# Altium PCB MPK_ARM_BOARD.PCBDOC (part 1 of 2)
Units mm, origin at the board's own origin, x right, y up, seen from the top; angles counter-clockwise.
Board outline 120 x 100 mm, 2 copper layers (Top Layer, Bottom Layer); 129 components, 139 nets, 526 pads, 161 vias.
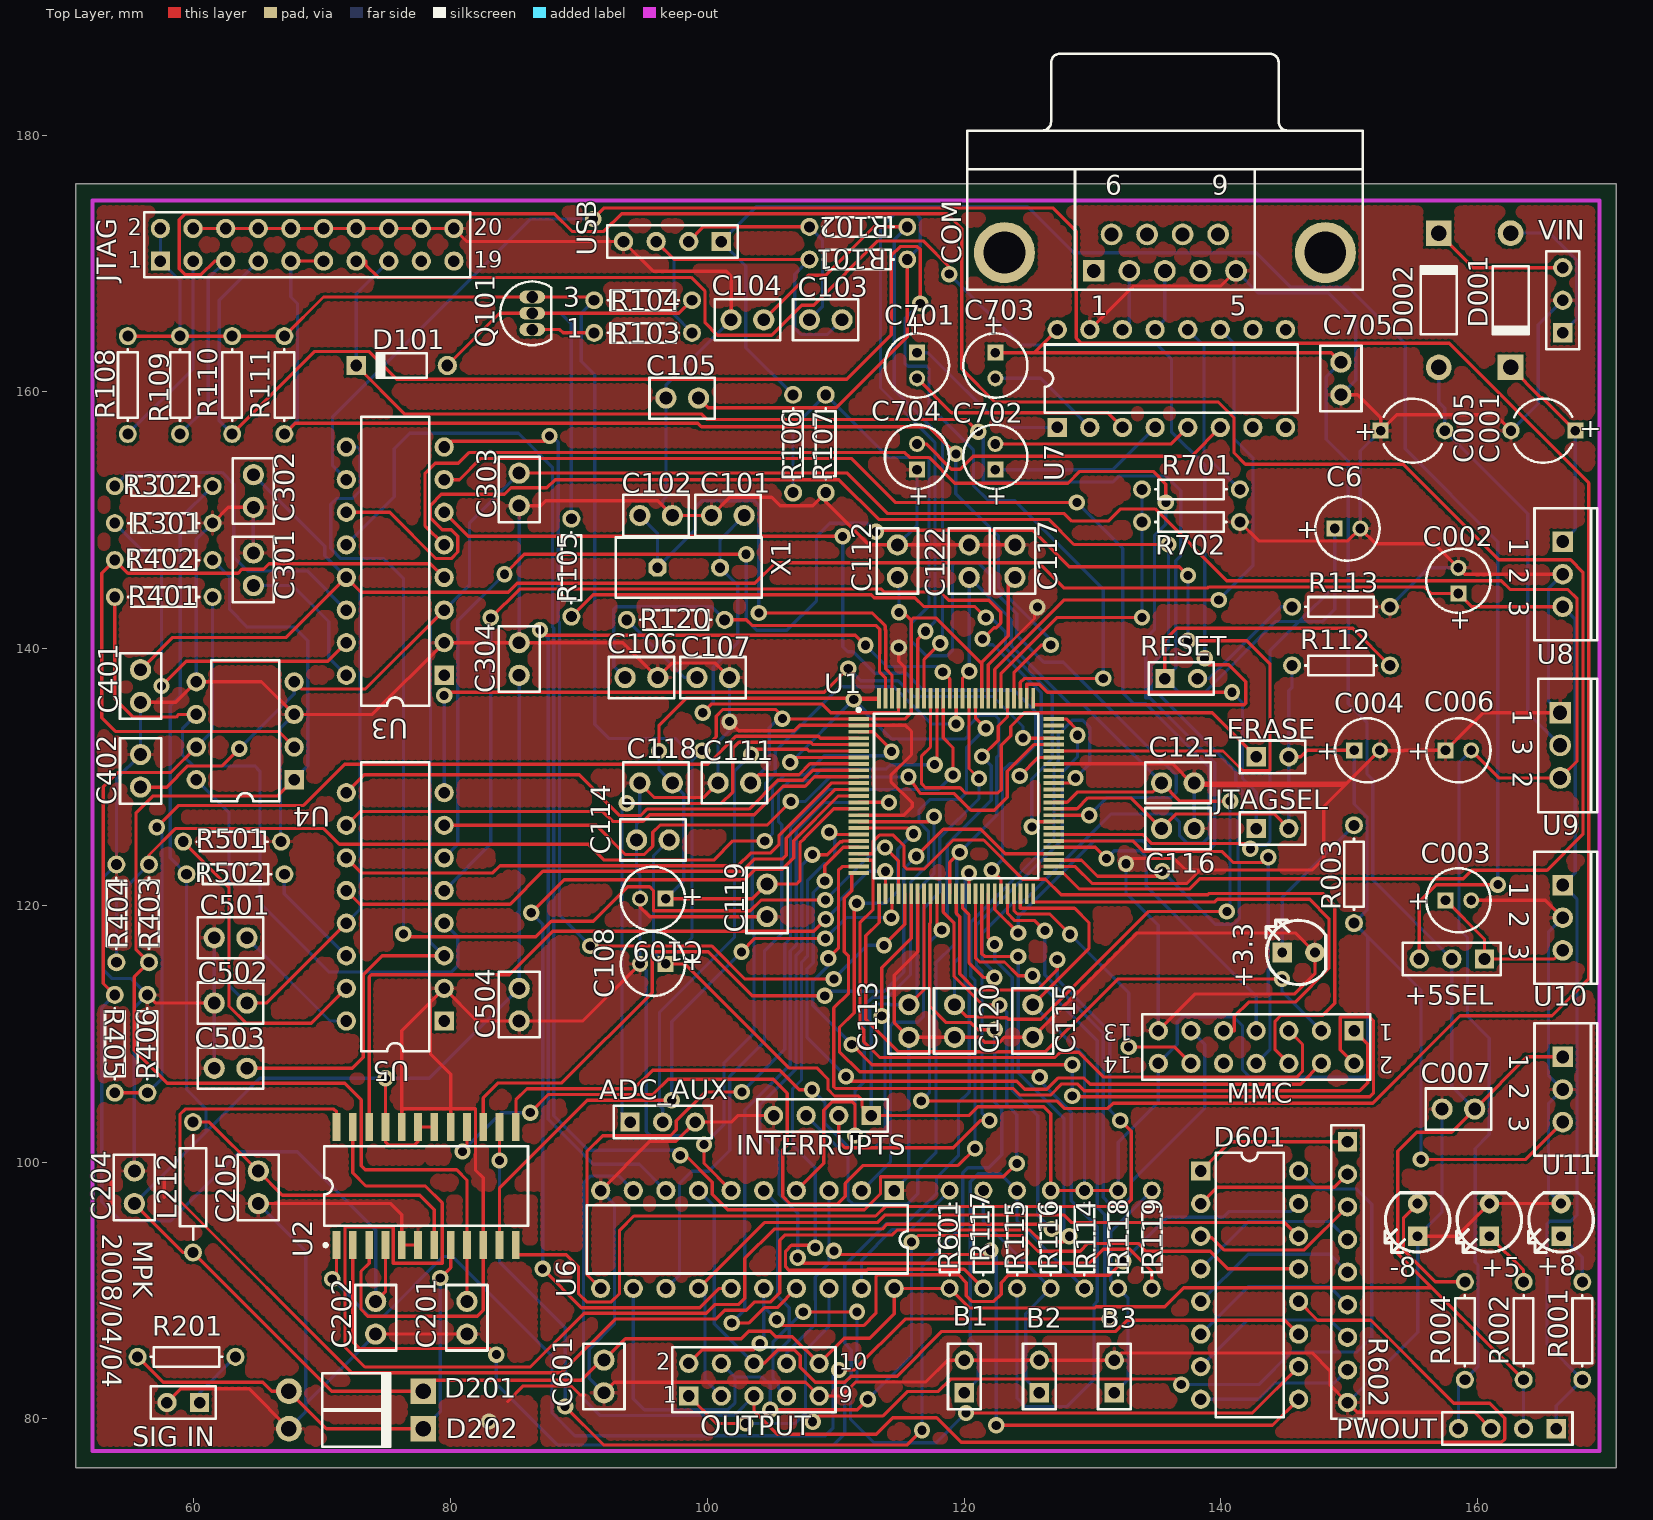
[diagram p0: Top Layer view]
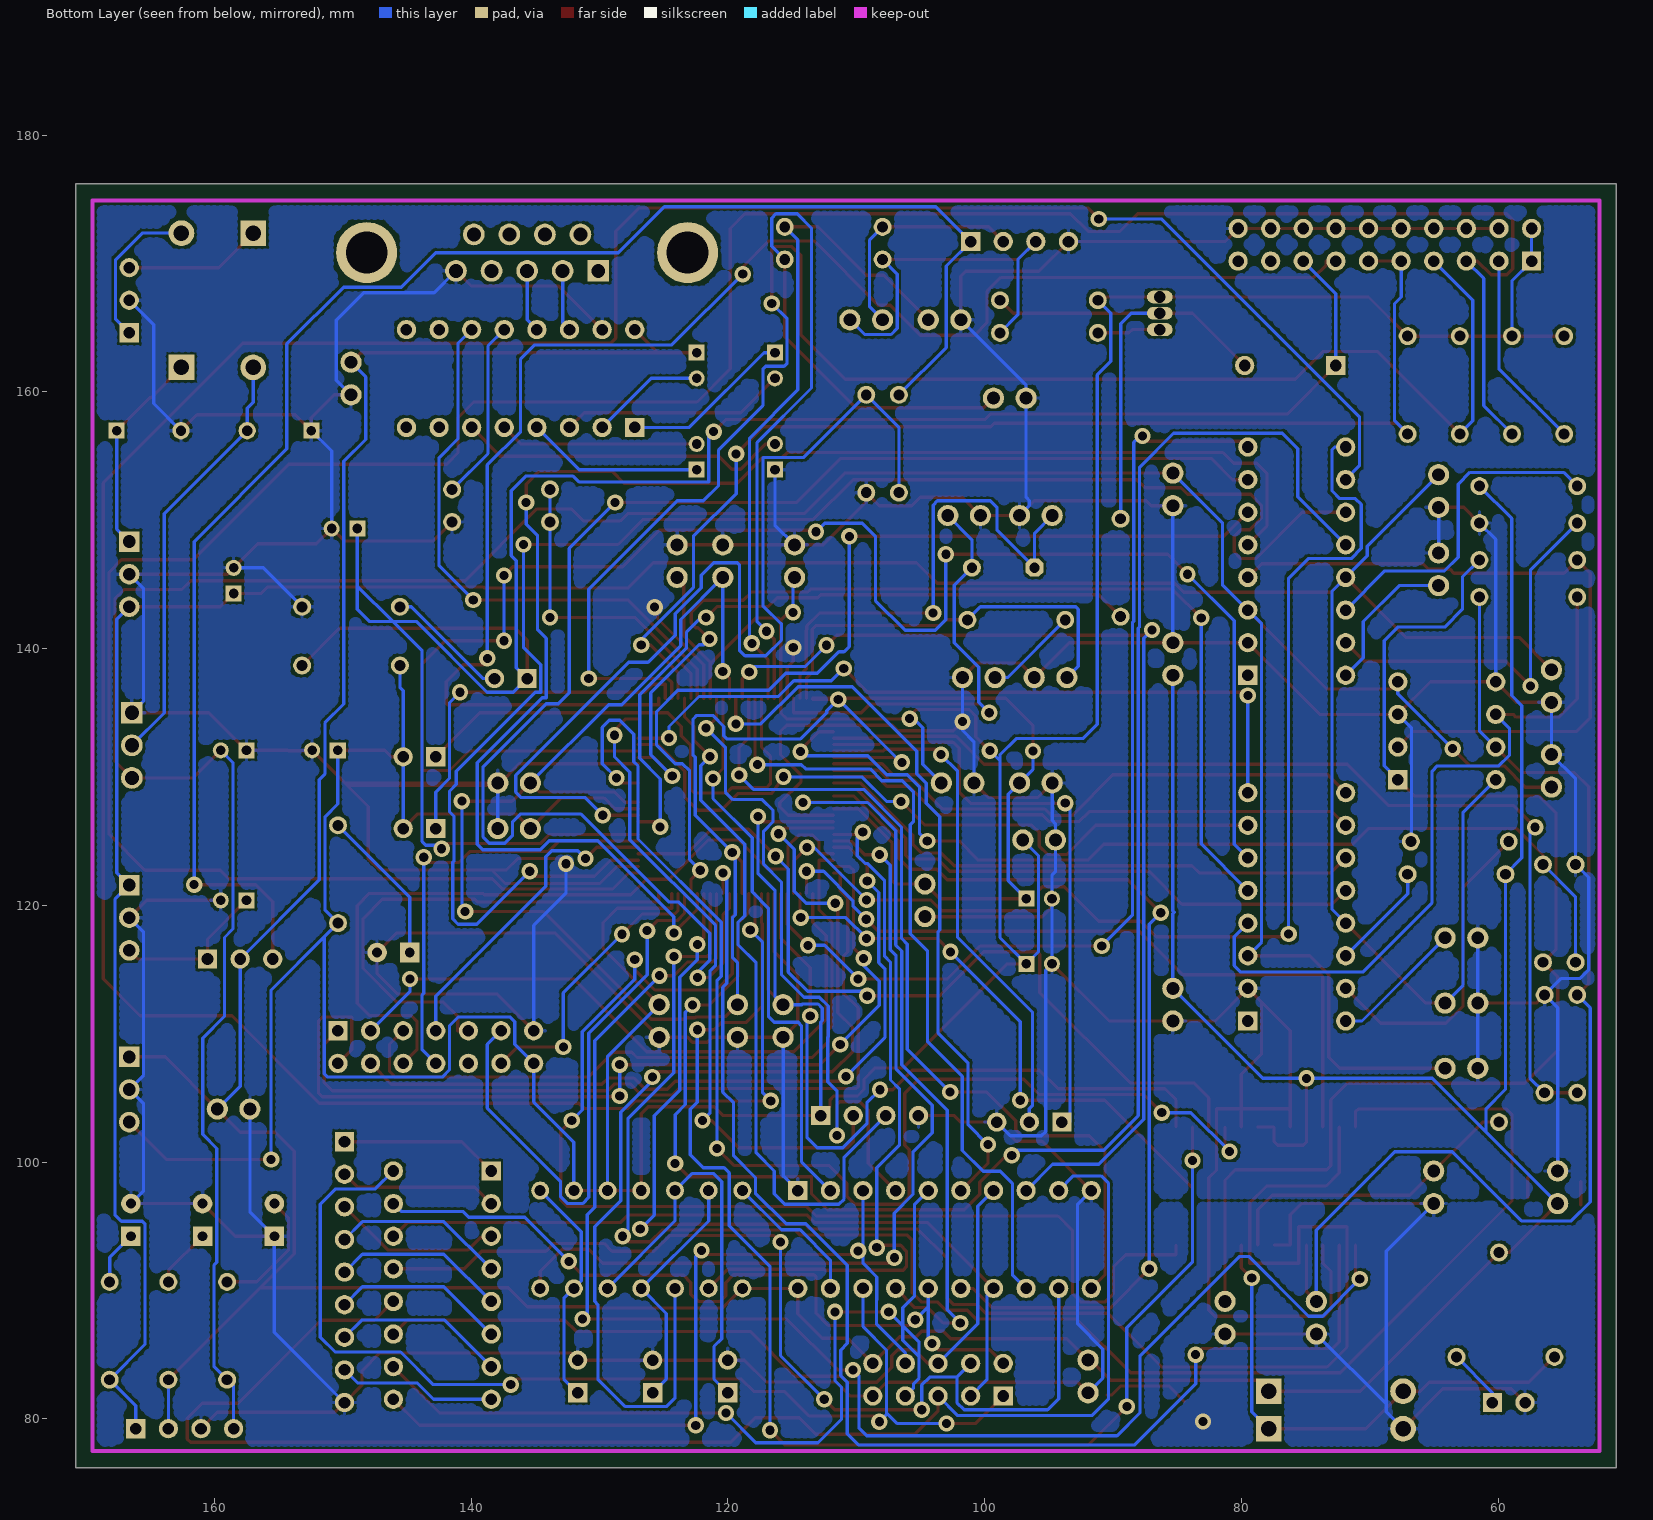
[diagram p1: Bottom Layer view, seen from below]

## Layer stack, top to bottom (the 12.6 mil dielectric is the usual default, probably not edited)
Top Layer: signal copper 0.0356
Dielectric: dielectric 0.32, FR-4, Dk 4.8
Bottom Layer: signal copper 0.0356

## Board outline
50.8,76.2 170.8,76.2 170.8,176.2 50.8,176.2

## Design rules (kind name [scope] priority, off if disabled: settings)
Clearance Clearance_1 [(InNet('-8V') AND InNet('+5V') AND InNet('+5V_USB') AND InNet('+8V'))] p1: gap=0.4
Clearance [All] p2: gap=0.18
ComponentClearance [All] p1: gap=0.254 collisioncheckmode=0
PolygonConnect [All] p1: connectstyle=Relief reliefconductorwidth=0.254 reliefentries=4 polygonreliefangle="90 Angle"
RoutingLayers [All] p1: top layer=Horizontal bottom layer=Vertical
RoutingVias [All] p1: holewidth=0.711 width=1.27 viastyle="Through Hole" minholewidth=0.711 minwidth=1.27 maxholewidth=0.711 maxwidth=1.27
SolderMaskExpansion [All] p1: expansion=0.102
TestPointUsage [All] p1: valid=0 allowmultiple=FALSE
Testpoint [All] p1: side=15 testpointundercomponent=TRUE minsize=1.016 maxsize=2.54 preferedsize=1.524 minholesize=0 maxholesize=1.016 preferedholesize=0.813 testpointgrid=0.025 style=1023 order=1234567890
Width Width_1 [(InNet('-8V') AND InNet('+8V') AND InNet('+5V')) AND InNet('+5V_USB')] p1: maxlimit=0.4 minlimit=0.3 preferedwidth=0.3
Width [All] p2: maxlimit=0.254 minlimit=0.18 preferedwidth=0.254
16 further rules are at their usual default settings.

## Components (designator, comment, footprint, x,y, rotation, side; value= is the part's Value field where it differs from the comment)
+3.3 "LED" LED 144.78,116.332 r90 top (schematic designator PW+3.3)
+5 "LED" LED 160.909,94.234 r180 top (schematic designator PW+5)
+5SEL "Header 3" HDR1X3 160.528,115.824 r180 top (schematic designator +5V_SELECT)
+8 "LED" LED 166.497,94.234 r180 top (schematic designator PW+8)
-8 "LED" LED 155.321,94.234 r180 top (schematic designator PW-8)
ADC_AUX "Header 3" HDR1X3 93.98,103.124 r0 top
B1 "Header 2" HDR1X2 120.015,82.042 r90 top
B2 "Header 2" HDR1X2 125.857,82.042 r90 top
B3 "Header 2" HDR1X2 131.699,82.042 r90 top
C001 "Cap Pol1" CAPPR5-5X5 165.1,156.972 r180 top
C002 "Cap Pol1" CAPPR2-5X6.8 158.496,145.288 r90 top
C003 "Cap Pol1" CAPPR2-5X6.8 158.496,120.396 r0 top
C004 "Cap Pol1" CAPPR2-5X6.8 151.384,132.08 r0 top
C005 "Cap Pol1" CAPPR5-5X5 154.94,156.972 r0 top
C6 "Cap Pol1" CAPPR2-5X6.8 149.86,149.352 r0 top
C006 "Cap Pol1" CAPPR2-5X6.8 158.496,132.079 r0 top
C007 "Cap" CAPR2.54-5.1X3.2 158.496,104.14 r0 top
C101 "Cap" CAPR2.54-5.1X3.2 101.6,150.368 r180 top
C102 "Cap" CAPR2.54-5.1X3.2 96.012,150.368 r0 top
C103 "Cap" CAPR2.54-5.1X3.2 109.22,165.608 r0 top
C104 "Cap" CAPR2.54-5.1X3.2 103.124,165.608 r0 top
C105 "Cap" CAPR2.54-5.1X3.2 98.044,159.512 r0 top
C106 "Cap" CAPR2.54-5.1X3.2 94.869,137.744 r180 top
C107 "Cap" CAPR2.54-5.1X3.2 100.457,137.744 r180 top
C108 "Cap Pol1" CAPPR2-5X6.8 95.758,115.443 r180 top
C109 "Cap Pol1" CAPPR2-5X6.8 95.758,120.523 r180 top
C111 "Cap" CAPR2.54-5.1X3.2 102.108,129.54 r0 top
C112 "Cap" CAPR2.54-5.1X3.2 114.808,146.812 r270 top
C113 "Cap" CAPR2.54-5.1X3.2 115.697,110.998 r90 top
C114 "Cap" CAPR2.54-5.1X3.2 95.758,125.095 r0 top
C115 "Cap" CAPR2.54-5.1X3.2 125.349,110.998 r90 top
C116 "Cap" CAPR2.54-5.1X3.2 136.652,125.984 r180 top
C117 "Cap" CAPR2.54-5.1X3.2 123.952,146.812 r270 top
C118 "Cap" CAPR2.54-5.1X3.2 96.012,129.54 r0 top
C119 "Cap" CAPR2.54-5.1X3.2 104.648,120.396 r90 top
C120 "Cap" CAPR2.54-5.1X3.2 119.253,110.998 r90 top
C121 "Cap" CAPR2.54-5.1X3.2 136.652,129.54 r180 top
C122 "Cap" CAPR2.54-5.1X3.2 120.396,146.812 r270 top
C201 "Cap" CAPR2.54-5.1X3.2 81.28,87.884 r90 top
C202 "Cap" CAPR2.54-5.1X3.2 74.168,87.884 r90 top
C204 "Cap" CAPR2.54-5.1X3.2 55.372,98.044 r270 top
C205 "Cap" CAPR2.54-5.1X3.2 65.024,98.044 r90 top
C301 "Cap" CAPR2.54-5.1X3.2 64.643,146.177 r270 top
C302 "Cap" CAPR2.54-5.1X3.2 64.643,152.273 r90 top
C303 "Cap" CAPR2.54-5.1X3.2 85.344,152.4 r270 top
C304 "Cap" CAPR2.54-5.1X3.2 85.344,139.192 r270 top
C401 "Cap" CAPR2.54-5.1X3.2 55.855,137.084 r90 top
C402 "Cap" CAPR2.54-5.1X3.2 55.855,130.48 r90 top
C501 "Cap" CAPR2.54-5.1X3.2 62.865,117.475 r0 top
C502 "Cap" CAPR2.54-5.1X3.2 62.865,112.395 r0 top
C503 "Cap" CAPR2.54-5.1X3.2 62.865,107.315 r180 top
C504 "Cap" CAPR2.54-5.1X3.2 85.344,112.268 r90 top
C601 "Cap" CAPR2.54-5.1X3.2 91.948,83.312 r90 top
C701 "Cap Pol1" CAPPR2-5X6.8 116.332,162.052 r270 top
C702 "Cap Pol1" CAPPR2-5X6.8 122.428,154.94 r90 top
C703 "Cap Pol1" CAPPR2-5X6.8 122.428,162.052 r270 top
C704 "Cap Pol1" CAPPR2-5X6.8 116.332,154.94 r90 top
C705 "Cap" CAPR2.54-5.1X3.2 149.352,161.036 r90 top
COM "D Connector 9" DSUB1.385-2H9 135.636,180.34 r0 top (schematic designator J1)
D001 "Diode 1N4007" DIO10.46-5.3x2.8 162.56,167.132 r270 top
D002 "Diode 1N4007" DIO10.46-5.3x2.8 156.972,167.132 r90 top
D101 "Diode 1N4148" DIO7.1-3.9x1.9 76.2,162.052 r180 top
D201 "Diode 1N4004" DIO10.46-5.3x2.8 72.644,82.169 r0 top
D202 "Diode 1N4004" DIO10.46-5.3x2.8 72.644,79.248 r0 top
D601 "Res Pack2" DIP-16 142.24,90.424 r270 top
ERASE "Header 2" HDR1X2 142.748,131.572 r0 top
INTERRUPTS "Header 4" HDR1X4 112.776,103.632 r180 top
JTAG "Header 10X2" HDR2X10 57.404,170.18 r0 top
JTAGSEL "Header 2" HDR1X2 142.748,125.984 r0 top
L212 "Res2" AXIAL-0.4 59.944,98.044 r90 top
MMC "Header 7X2" HDR2X7 150.368,110.236 r180 top
OUTPUT "Header 5X2" HDR2X5 98.552,81.788 r0 top
PWOUT "Header 4" HDR1X4 166.116,79.248 r180 top
Q101 "2N3904" BCY-W3/E4 86.36,166.116 r0 top
R001 "Res1" AXIAL-0.3 168.148,86.868 r270 top
R002 "Res1" AXIAL-0.3 163.576,86.868 r270 top
R003 "Res1" AXIAL-0.3 150.368,122.428 r270 top
R004 "Res1" AXIAL-0.3 159.004,86.868 r270 top
R101 "Res1" AXIAL-0.3 111.76,170.307 r180 top
R102 "Res1" AXIAL-0.3 111.76,172.847 r180 top
R103 "Res1" AXIAL-0.3 94.996,164.592 r180 top
R104 "Res1" AXIAL-0.3 94.996,167.132 r180 top
R105 "Res1" AXIAL-0.3 89.408,146.304 r90 top
R106 "Res1" AXIAL-0.3 106.68,155.956 r90 top
R107 "Res1" AXIAL-0.3 109.22,155.956 r90 top
R108 "Res1" AXIAL-0.3 54.864,160.528 r90 top
R109 "Res1" AXIAL-0.3 58.928,160.528 r90 top
R110 "Res1" AXIAL-0.3 62.992,160.528 r90 top
R111 "Res1" AXIAL-0.3 67.056,160.528 r90 top
R112 "Res1" AXIAL-0.3 149.352,138.684 r180 top
R113 "Res1" AXIAL-0.3 149.352,143.256 r180 top
R114 "Res1" AXIAL-0.3 129.371,93.98 r90 top
R115 "Res1" AXIAL-0.3 124.121,93.98 r90 top
R116 "Res1" AXIAL-0.3 126.746,93.98 r90 top
R117 "Res1" AXIAL-0.3 121.497,93.98 r90 top
R118 "Res1" AXIAL-0.3 131.995,93.98 r90 top
R119 "Res1" AXIAL-0.3 134.62,93.98 r90 top
R120 "Res1" AXIAL-0.3 97.536,142.24 r0 top
R201 "Res1" AXIAL-0.3 59.436,84.836 r180 top
R301 "Res1" AXIAL-0.3 57.658,149.775 r180 top
R302 "Res1" AXIAL-0.3 57.658,152.654 r180 top
R401 "Res1" AXIAL-0.3 57.658,144.018 r180 top
R402 "Res1" AXIAL-0.3 57.658,146.897 r180 top
R403 "Res1" AXIAL-0.3 56.515,119.38 r270 top
R404 "Res1" AXIAL-0.3 53.975,119.38 r270 top
R405 "Res1" AXIAL-0.3 53.848,109.22 r90 top
R406 "Res1" AXIAL-0.3 56.388,109.22 r270 top
R501 "Res1" AXIAL-0.3 62.992,124.968 r180 top
R502 "Res1" AXIAL-0.3 63.246,122.428 r0 top
R601 "Res1" AXIAL-0.3 118.872,93.98 r270 top
R602 "Header 9" HDR1X9 149.86,101.6 r270 top
R701 "Res1" AXIAL-0.3 137.668,152.4 r180 top
R702 "Res1" AXIAL-0.3 137.668,149.86 r180 top
RESET "Header 2" HDR1X2 135.636,137.668 r0 top
"SIG IN" "Header 2" HDR1X2 60.452,81.28 r180 top (schematic designator "SIGNAL IN")
U1 "AT91SAM7X256" LQFP100 119.38,128.524 r0 top
U2 "TDA8714" SOP24 70.104,94.996 r90 top
U3 "DAC0808LCN" N16A 75.692,146.812 r90 top
U4 "AD706AN" N-8_A 64.008,133.604 r90 top
U5 "DAC0808LCN" N16A 75.692,119.888 r90 top
U6 "SN74HC244N" N020 103.124,93.98 r180 top
U7 "MAX232ACPE" PE16A 136.144,161.036 r0 top
U8 "MC78M08BT" 221A-04 166.624,145.796 r270 top
U9 "L7908ACV" TO220V 166.424,132.469 r270 top
U10 "MC7805ACT" 221A-04 166.624,119.041 r270 top
U11 "LM340T-18" 221A-04 166.624,105.664 r270 top
USB "Header 4" HDR1X4 101.092,171.704 r180 top
VIN "Header 3" HDR1X3 166.624,164.592 r90 top
X1 "ECS-10-13-1" HC-49U 98.552,146.304 r0 top

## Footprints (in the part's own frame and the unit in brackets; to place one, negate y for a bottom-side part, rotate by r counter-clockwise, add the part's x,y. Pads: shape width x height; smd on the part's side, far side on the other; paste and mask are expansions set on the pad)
221A-04 [mm] "TO, Thru-Hole, Vertical, Heatsink Mounted; 3 In-Line Leads; Pitch 2.54 mm"
  rect 1.6x1.6 hole 1: 1(-2.54,0)
  round 1.6 hole 1: 2(0,0) 3(2.54,0)
  silkscreen extent -5.15,-2.2 5.15,2.7
AXIAL-0.3 [mm]
  round 1.4 hole 0.85: 1(-3.81,0) 2(3.81,0)
  silkscreen extent -2.77,-0.76 2.77,0.76
AXIAL-0.4 [mm]
  round 1.4 hole 0.85: 1(-5.08,0) 2(5.08,0)
  silkscreen extent -4.06,-1.02 4.06,1.02
BCY-W3/E4 [mm]
  oval 2x1 hole 0.9: 1(0,-1.27) 2(0,0) 3(0,1.27)
  silkscreen extent -2.48,-2.48 1.5,2.48
CAPPR2-5X6.8 [mm]
  rect 1.25x1.25 hole 0.75: 1(-1,0)
  round 1.25 hole 0.75: 2(1,0)
  silkscreen extent -2.5,-2.5 2.5,2.5
CAPPR5-5X5 [mm]
  rect 1.25x1.25 hole 0.75: 1(-2.5,0)
  round 1.35 hole 0.8: 2(2.5,0)
  silkscreen extent -2.26,-2.5 2.27,2.5
CAPR2.54-5.1X3.2 [mm]
  round 1.65 hole 1: 1(-1.27,0) 2(1.27,0)
  silkscreen extent -2.55,-1.6 2.55,1.6
DIO7.1-3.9x1.9 [mm]
  round 1.5 hole 0.9: 1(-3.55,0)
  rect 1.5x1.5 hole 0.9: 2(3.55,0)
  silkscreen extent -1.95,-0.95 2.05,0.95
DIO10.46-5.3x2.8 [mm]
  round 2 hole 1.2: 1(-5.23,0)
  rect 2x2 hole 1.2: 2(5.23,0)
  silkscreen extent -2.65,-1.4 2.75,1.4
DIP-16 [mm]
  rect 1.5x1.5 hole 0.9: 1(-8.89,-3.81)
  round 1.5 hole 0.9: 2(-6.35,-3.81) 3(-3.81,-3.81) 4(-1.27,-3.81) 5(1.27,-3.81) 6(3.81,-3.81) 7(6.35,-3.81) 8(8.89,-3.81) 9(8.89,3.81) 10(6.35,3.81) 11(3.81,3.81) 12(1.27,3.81) 13(-1.27,3.81) 14(-3.81,3.81) 15(-6.35,3.81) 16(-8.89,3.81)
  silkscreen extent -10.3,-2.65 10.3,2.65
DSUB1.385-2H9 [mm] "Connector; D Subminiature; 9 Position; Right Angle; Pitch 1.385 mm"
  rect 1.69x1.69 hole 1.09: 1(-5.54,-10.92)
  round 1.69 hole 1.09: 2(-2.77,-10.92) 3(0,-10.92) 4(2.77,-10.92) 5(5.54,-10.92) 6(-4.155,-8.08) 7(-1.385,-8.08) 8(1.385,-8.08) 9(4.155,-8.08)
  round 4.76 hole 3.26: 10(-12.495,-9.5) 11(12.495,-9.5)
  silkscreen extent -15.4,-12.4 15.4,6
HC-49U [mm] "Quartz Crystal, Thru-Hole; 2 Leads; Body 11.35 x 4.65 x 13.46 mm (LxWxH max)"
  oct 1.4x1.4 hole 0.8: 1(-2.44,0)
  round 1.4 hole 0.8: 2(2.44,0)
  silkscreen extent -5.7,-2.35 5.7,2.35
HDR1X2 [mm] "Connector; Header; 2 Position"
  rect 1.5x1.5 hole 0.9: 1(0,0)
  round 1.5 hole 0.9: 2(2.54,0)
  silkscreen extent -1.27,-1.27 3.81,1.27
HDR1X3 [mm] "Connector; Header; 3 Position"
  rect 1.5x1.5 hole 0.9: 1(0,0)
  round 1.5 hole 0.9: 2(2.54,0) 3(5.08,0)
  silkscreen extent -1.27,-1.27 6.35,1.27
HDR1X4 [mm] "Connector; Header; 4 Position"
  rect 1.5x1.5 hole 0.9: 1(0,0)
  round 1.5 hole 0.9: 2(2.54,0) 3(5.08,0) 4(7.62,0)
  silkscreen extent -1.27,-1.27 8.89,1.27
HDR1X9 [mm] "Connector; Header; 9 Position"
  rect 1.5x1.5 hole 0.9: 1(0,0)
  round 1.5 hole 0.9: 2(2.54,0) 3(5.08,0) 4(7.62,0) 5(10.16,0) 6(12.7,0) 7(15.24,0) 8(17.78,0) 9(20.32,0)
  silkscreen extent -1.27,-1.27 21.59,1.27
HDR2X5 [mm] "Connector; Header; 5x2 Position"
  rect 1.5x1.5 hole 0.9: 1(0,0)
  round 1.5 hole 0.9: 2(0,2.54) 3(2.54,0) 4(2.54,2.54) 5(5.08,0) 6(5.08,2.54) 7(7.62,0) 8(7.62,2.54) 9(10.16,0) 10(10.16,2.54)
  silkscreen extent -1.27,-1.27 11.43,3.81
HDR2X7 [mm] "Connector; Header; 7x2 Position"
  rect 1.5x1.5 hole 0.9: 1(0,0)
  round 1.5 hole 0.9: 2(0,2.54) 3(2.54,0) 4(2.54,2.54) 5(5.08,0) 6(5.08,2.54) 7(7.62,0) 8(7.62,2.54) 9(10.16,0) 10(10.16,2.54) 11(12.7,0) 12(12.7,2.54) 13(15.24,0) 14(15.24,2.54)
  silkscreen extent -1.27,-1.27 16.51,3.81
HDR2X10 [mm] "Connector; Header; 10x2 Position"
  rect 1.5x1.5 hole 0.9: 1(0,0)
  round 1.5 hole 0.9: 2(0,2.54) 3(2.54,0) 4(2.54,2.54) 5(5.08,0) 6(5.08,2.54) 7(7.62,0) 8(7.62,2.54) 9(10.16,0) 10(10.16,2.54) 11(12.7,0) 12(12.7,2.54) 13(15.24,0) 14(15.24,2.54) 15(17.78,0) 16(17.78,2.54) 17(20.32,0) 18(20.32,2.54) 19(22.86,0) 20(22.86,2.54)
  silkscreen extent -1.27,-1.27 24.13,3.81
LED [mil]
  rect 60x60 hole 30: 1(0,0)
  round 60 hole 30: 2(0,-100)
  silkscreen extent -99,-134 100,50
LQFP100 [mm] "QFP; 100 Leads; Body 14 x 14 mm; Pitch 0.5 mm"
  rect 1.6x0.3 smd: 1(-7.6,6) 2(-7.6,5.5) 3(-7.6,5) 4(-7.6,4.5) 5(-7.6,4) 6(-7.6,3.5) 7(-7.6,3) 8(-7.6,2.5) 9(-7.6,2) 10(-7.6,1.5) 11(-7.6,1) 12(-7.6,0.5) 13(-7.6,0) 14(-7.6,-0.5) 15(-7.6,-1) 16(-7.6,-1.5) 17(-7.6,-2) 18(-7.6,-2.5) 19(-7.6,-3) 20(-7.6,-3.5) 21(-7.6,-4) 22(-7.6,-4.5) 23(-7.6,-5) 24(-7.6,-5.5) 25(-7.6,-6) 51(7.6,-6) 52(7.6,-5.5) 53(7.6,-5) 54(7.6,-4.5) 55(7.6,-4) 56(7.6,-3.5) 57(7.6,-3) 58(7.6,-2.5) 59(7.6,-2) 60(7.6,-1.5) 61(7.6,-1) 62(7.6,-0.5) 63(7.6,0) 64(7.6,0.5) 65(7.6,1) 66(7.6,1.5) 67(7.6,2) 68(7.6,2.5) 69(7.6,3) 70(7.6,3.5) 71(7.6,4) 72(7.6,4.5) 73(7.6,5) 74(7.6,5.5) 75(7.6,6)
  rect 0.3x1.6 smd: 26(-6,-7.6) 27(-5.5,-7.6) 28(-5,-7.6) 29(-4.5,-7.6) 30(-4,-7.6) 31(-3.5,-7.6) 32(-3,-7.6) 33(-2.5,-7.6) 34(-2,-7.6) 35(-1.5,-7.6) 36(-1,-7.6) 37(-0.5,-7.6) 38(0,-7.6) 39(0.5,-7.6) 40(1,-7.6) 41(1.5,-7.6) 42(2,-7.6) 43(2.5,-7.6) 44(3,-7.6) 45(3.5,-7.6) 46(4,-7.6) 47(4.5,-7.6) 48(5,-7.6) 49(5.5,-7.6) 50(6,-7.6) 76(6,7.6) 77(5.5,7.6) 78(5,7.6) 79(4.5,7.6) 80(4,7.6) 81(3.5,7.6) 82(3,7.6) 83(2.5,7.6) 84(2,7.6) 85(1.5,7.6) 86(1,7.6) 87(0.5,7.6) 88(0,7.6) 89(-0.5,7.6) 90(-1,7.6) 91(-1.5,7.6) 92(-2,7.6) 93(-2.5,7.6) 94(-3,7.6) 95(-3.5,7.6) 96(-4,7.6) 97(-4.5,7.6) 98(-5,7.6) 99(-5.5,7.6) 100(-6,7.6)
  silkscreen extent -7.72,-6.4 6.4,6.82
N16A [mm] "DIP; 16 Leads; Row Spacing 7.62 mm; Pitch 2.54 mm"
  rect 1.5x1.5 hole 0.9: 1(-8.89,-3.81)
  round 1.5 hole 0.9: 2(-6.35,-3.81) 3(-3.81,-3.81) 4(-1.27,-3.81) 5(1.27,-3.81) 6(3.81,-3.81) 7(6.35,-3.81) 8(8.89,-3.81) 9(8.89,3.81) 10(6.35,3.81) 11(3.81,3.81) 12(1.27,3.81) 13(-1.27,3.81) 14(-3.81,3.81) 15(-6.35,3.81) 16(-8.89,3.81)
  silkscreen extent -11.25,-2.65 11.25,2.65
N020 [mm] "DIP; 20 Leads; Row Spacing 7.62 mm; Pitch 2.54 mm"
  rect 1.5x1.5 hole 0.9: 1(-11.43,-3.81)
  round 1.5 hole 0.9: 2(-8.89,-3.81) 3(-6.35,-3.81) 4(-3.81,-3.81) 5(-1.27,-3.81) 6(1.27,-3.81) 7(3.81,-3.81) 8(6.35,-3.81) 9(8.89,-3.81) 10(11.43,-3.81) 11(11.43,3.81) 12(8.89,3.81) 13(6.35,3.81) 14(3.81,3.81) 15(1.27,3.81) 16(-1.27,3.81) 17(-3.81,3.81) 18(-6.35,3.81) 19(-8.89,3.81) 20(-11.43,3.81)
  silkscreen extent -12.5,-2.65 12.5,2.65
N-8_A [mm] "DIP; 8 Leads; Row Spacing 7.62 mm; Pitch 2.54 mm"
  rect 1.5x1.5 hole 0.9: 1(-3.81,-3.81)
  round 1.5 hole 0.9: 2(-1.27,-3.81) 3(1.27,-3.81) 4(3.81,-3.81) 5(3.81,3.81) 6(1.27,3.81) 7(-1.27,3.81) 8(-3.81,3.81)
  silkscreen extent -5.5,-2.65 5.5,2.65
PE16A [mm] "DIP; 16 Leads; Row Spacing 7.62 mm; Pitch 2.54 mm"
  rect 1.5x1.5 hole 0.9: 1(-8.89,-3.81)
  round 1.5 hole 0.9: 2(-6.35,-3.81) 3(-3.81,-3.81) 4(-1.27,-3.81) 5(1.27,-3.81) 6(3.81,-3.81) 7(6.35,-3.81) 8(8.89,-3.81) 9(8.89,3.81) 10(6.35,3.81) 11(3.81,3.81) 12(1.27,3.81) 13(-1.27,3.81) 14(-3.81,3.81) 15(-6.35,3.81) 16(-8.89,3.81)
  silkscreen extent -9.85,-2.65 9.85,2.65
SOP24 [mm]
  rect 2.2x0.6 smd: 1(-1.453,-1.016) 2(-1.453,-2.286) 3(-1.453,-3.556) 4(-1.453,-4.826) 5(-1.453,-6.096) 6(-1.453,-7.366) 7(-1.453,-8.636) 8(-1.453,-9.906) 9(-1.453,-11.176) 10(-1.453,-12.446) 11(-1.453,-13.716) 12(-1.453,-14.986) 13(7.747,-14.986) 14(7.747,-13.716) 15(7.747,-12.446) 16(7.747,-11.176) 17(7.747,-9.906) 18(7.747,-8.636) 19(7.747,-7.366) 20(7.747,-6.096) 21(7.747,-4.826) 22(7.747,-3.556) 23(7.747,-2.286) 24(7.747,-1.016)
  silkscreen extent -1.58,-15.93 6.25,-0.04
TO220V [mm] "TO, Thru-Hole, Vertical, Heatsink Mounted; 3 In-Line Leads; Pitch 2.54 mm; Pin sequence 1, 3, 2"
  rect 1.7x1.7 hole 1.1: 1(-2.54,0)
  round 1.7 hole 1.1: 2(2.54,0) 3(0,0)
  silkscreen extent -5.2,-1.7 5.2,2.9

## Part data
+5SEL ADC_AUX VIN: "Header, 3-Pin"
B1 B2 B3 RESET: library part PushBotom
C001 C002 C003 C004 C005 C6 C006 C108 C109 C701 C702 C703 C704: "Polarized Capacitor (Radial)"
C007 C101 C102 C103 C104 C105 C106 C107 C111 C112 C113 C114 C115 C116 C117 C118 C119 C120 C121 C122 C201 C202 C204 C205 C301 C302 C303 C304 C401 C402 C501 C502 C503 C504 C601 C705: "Capacitor"
COM: "Receptacle Assembly, 9 Position, Right Angle"
D001 D002 D201 D202: "1 Amp General Purpose Rectifier"
D101: "High Conductance Fast Diode"
D601: "Resistor Array - Parts"
ERASE JTAGSEL "SIG IN": "Header, 2-Pin"
INTERRUPTS PWOUT USB: "Header, 4-Pin"
JTAG: "Header, 10-Pin, Dual row"
L212 R001 R002 R003 R004 R101 R102 R103 R104 R105 R106 R107 R108 R109 R110 R111 R112 R113 R114 R115 R116 R117 R118 R119 R120 R201 R301 R302 R401 R402 R403 R404 R405 R406 R501 R502 R601 R701 R702: "Resistor"
MMC: "Header, 7-Pin, Dual row"
OUTPUT: "Header, 5-Pin, Dual row"
Q101: "NPN General Purpose Amplifier"
R602: "Header, 9-Pin"
U1: library part AT91SAM7X512/256/128, "Atmel ARM Core 32 Microcontroller"
U3 U5: "8-Bit D/A Converter"
U4: "Dual Picoampere Input Current Bipolar Operational Amplifier"
U6: "Octal Buffer and Line Driver with 3-State Outputs"
U7: "+5V Powered, Multi-Channel RS-232 Driver/Receiver"
U8: "3-Terminal Medium-Current Positive Fixed Voltage Regulator"
U9: "2% Negative Voltage Regulator"
U10 U11: "3-Terminal Positive Fixed Voltage Regulator"
X1: "Crystal Oscillator"

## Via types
v1: diameter 1.27, hole 0.711, Top Layer to Bottom Layer, 161 vias

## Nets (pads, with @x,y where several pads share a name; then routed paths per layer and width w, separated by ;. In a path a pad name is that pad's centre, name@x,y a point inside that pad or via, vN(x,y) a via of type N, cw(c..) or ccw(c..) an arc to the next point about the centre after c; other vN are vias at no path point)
+1.8V: C109.1 C118.2 C119.2 C120.2 C121.2 C122.2 U1.7 U1.15 U1.37 U1.62 U1.87 U1.100 | length 190.8
  Top Layer w0.254: v1(96.241,132.029) 96.241,134.036 98.349,136.144 111.404,136.144 112.293,136.144 113.38,136.144 U1.100@113.38,136.124 U1.100@113.38,136.093 ; C109.1@96.758,120.523 103.505,120.523 C119.2@104.648,121.666 106.959,121.666 107.213,121.92 107.213,124.866 107.544,125.197 ; v1(106.451,131.14) 106.835,131.524 U1.7@111.78,131.524 ; 107.544,125.239 109.829,127.524 U1.15@111.78,127.524 ; v1(111.404,136.042) 113.38,136.042 U1.100@113.38,136.093 ; 112.293,136.093 U1.100@113.38,136.093 ; U1.37@118.88,120.924 118.88,123.35 v1(119.659,124.13) v1@119.659,123.927 ; C120.2@119.253,112.268 120.167,111.354 120.879,111.354 120.929,111.303 122.504,111.303 122.555,111.252 123.317,111.252 123.444,111.125 125.984,111.125 134.391,119.532 v1(140.462,119.532) ; U1.87@119.88,136.124 119.88,137.711 v1(120.396,138.227) ; U1.62@126.98,128.024 128.016,128.024 128.821,128.829 134.671,128.829 C121.2@135.382,129.54 136.804,128.118 v1(140.716,128.118)
  Bottom Layer w0.254: v1(96.241,132.029) 96.241,130.581 C118.2@97.282,129.54 98.171,128.651 98.171,121.936 C109.1@96.758,120.523 ; v1(106.451,131.14) 106.477,131.115 v1(111.404,136.042) 112.293,135.153 112.293,135.014 114.338,132.969 120.091,132.969 120.32,133.198 120.32,133.932 121.186,134.798 122.428,134.798 122.707,134.518 122.707,131.703 122.551,131.547 122.551,127.021 v1(119.659,124.13) ; C120.2@119.253,112.268 119.253,115.559 119.645,115.951 119.645,119.039 119.431,119.253 119.431,123.698 v1@119.659,123.927 ; v1(120.396,138.227) C122.2@120.396,145.542 123.67,142.268 123.67,140.233 128.268,135.636 129.286,135.636 C121.2@135.382,129.54 ; v1(140.462,119.532) 140.716,119.786 v1(140.716,128.118)
+3.3V: C004.1 C108.1 C111.2 C112.2 C113.2 C114.2 C115.2 C116.2 C117.2 ERASE.2 INTERRUPTS.1 JTAG.1 JTAG.2 JTAGSEL.2 MMC.14 Q101.3 R003.2 R104.2 R108.2 R109.2 R110.2 R111.2 R112.2 R114.2 R116.2 R118.2 U1.1 U1.8 U1.17 U1.33 U1.48 U1.61 U1.84 U1.95 U11.3 | length 432.8
  Top Layer w0.254: R108.2@54.864,164.338 R109.2@58.928,164.338 R110.2@62.992,164.338 R111.2@67.056,164.338 70.104,167.386 Q101.3@86.36,167.386 90.932,167.386 R104.2@91.186,167.132 ; C108.1@96.758,115.443 98.249,115.443 106.352,107.34 108.534,107.34 109.398,106.477 109.398,105.664 109.906,105.156 111.76,105.156 112.039,104.877 112.039,104.369 INTERRUPTS.1@112.776,103.632 120.371,103.632 121.056,104.318 126.213,104.318 126.746,103.784 R116.2@126.746,97.79 R114.2@129.371,97.79 R118.2@131.995,97.79 ; v1(99.593,132.055) 100.686,133.147 100.686,134.749 101.194,135.257 105.337,135.257 v1@106.07,134.524 ; C111.2@103.378,129.54 104.013,130.175 107.139,130.175 107.988,131.024 U1.8@111.78,131.024 ; v1(105.842,134.544) 105.862,134.524 U1.1@111.78,134.524 115.418,134.524 115.88,134.986 U1.95@115.88,136.124 115.88,142.215 ; U1.17@111.78,126.524 117.257,126.524 v1(117.657,126.924) ; v1(114.935,142.824) 115.27,142.824 115.88,142.215 ; C113.2@115.697,112.268 116.88,113.451 U1.33@116.88,120.924 ; U1.84@121.38,136.124 121.38,138.931 123.444,140.995 123.444,145.034 C117.2@123.952,145.542 ; 121.38,138.811 117.799,142.392 116.058,142.392 115.88,142.215 ; U1.48@124.38,120.924 124.38,119.786 128.6,119.786 129.718,118.669 129.718,116.637 C115.2@125.349,112.268 ; U1.61@126.98,127.524 128.794,127.524 129.642,128.372 132.994,128.372 C116.2@135.382,125.984 136.525,127.127 144.145,127.127 JTAGSEL.2@145.288,125.984 ; ERASE.2@145.288,131.572 146.228,131.572 146.736,132.08 C004.1@150.384,132.08 ; v1(155.575,100.203) 163.703,100.203 U11.3@166.624,103.124
  Bottom Layer w0.254: JTAG.2@57.404,172.72 JTAG.1@57.404,170.18 58.928,168.656 R109.2@58.928,164.338 ; R104.2@91.186,167.132 90.17,166.116 90.17,162.382 91.237,161.315 91.237,134.112 92.354,132.994 97.536,132.994 98.806,131.724 98.806,117.491 C108.1@96.758,115.443 95.809,116.392 95.809,123.876 C114.2@97.028,125.095 ; 98.806,131.267 v1(99.593,132.055) ; C111.2@103.378,129.54 104.826,130.988 104.826,133.833 105.537,134.544 v1(105.842,134.544) ; INTERRUPTS.1@112.776,103.632 112.776,110.896 112.645,111.028 112.645,111.989 112.977,112.321 114.198,112.321 114.251,112.268 C113.2@115.697,112.268 116.332,112.903 116.332,121.183 117.657,122.509 v1(117.657,126.924) ; C112.2@114.808,145.542 114.935,145.415 v1@114.935,142.773 ; C115.2@125.349,112.268 129.371,108.246 R114.2@129.371,97.79 ; R118.2@131.995,97.79 131.995,101.549 135.128,104.682 MMC.14@135.128,107.696 136.601,109.169 136.601,110.947 136.957,111.303 141.021,111.303 141.681,110.642 141.681,107.188 142.24,106.629 151.181,106.629 151.435,106.883 151.435,117.551 ; JTAGSEL.2@145.288,125.984 ERASE.2@145.288,131.572 145.288,136.728 145.542,136.982 R112.2@145.542,138.684 ; C004.1@150.384,132.08 150.384,127.898 151.375,126.907 151.375,119.625 R003.2@150.368,118.618 151.435,117.551 ; v1(155.575,100.203) 155.575,113.411 151.435,117.551
+5V: +5SEL.2 C007.2 C204.2 C304.2 C504.2 C601.2 C703.1 C705.2 D201.2 L212.1 OUTPUT.10 PWOUT.2 R002.2 R302.1 R502.1 R601.2 U2.18 U2.19 U2.21 U6.20 U7.16 U11.1 | length 374
  Top Layer w0.254: C204.2@55.372,96.774 59.182,92.964 L212.1@59.944,92.964 70.739,82.169 D201.2@77.874,82.169 78.712,83.007 90.17,83.007 91.745,84.582 C601.2@91.948,84.582 93.624,86.258 102.641,86.258 103.226,86.843 104.902,86.843 105.334,86.411 106.629,86.411 OUTPUT.10@108.712,84.328 110.668,86.284 112.649,86.284 114.554,88.189 U6.20@114.554,90.17 R601.2@118.872,90.17 120.396,88.646 130.175,88.646 130.277,88.748 135.636,88.748 137.109,90.221 156.413,90.221 ; v1(74.93,106.528) U2.21@74.93,102.743 74.93,101.575 75.184,101.321 77.165,101.321 77.47,101.625 U2.19@77.47,102.743 U2.18@78.74,102.743 ; C703.1@122.428,163.052 125.46,163.052 ; U7.16@127.254,164.846 125.46,163.052 ; C705.2@149.352,162.306 148.606,163.052 125.46,163.052 ; R002.2@163.576,83.058 156.413,90.221 ; U11.1@166.624,108.204 163.83,108.204 C007.2@159.766,104.14 157.963,102.337 155.245,102.337 153.772,100.863 153.772,92.862 156.413,90.221
  Bottom Layer w0.254: C204.2@55.372,96.774 60.96,102.362 ; R302.1@61.468,152.654 58.953,150.139 58.953,136.347 58.166,135.56 58.166,123.698 R502.1@59.436,122.428 59.436,105.664 60.96,104.14 60.96,102.362 ; C304.2@85.344,137.922 85.344,119.583 85.23,119.469 85.344,119.355 C504.2@85.344,113.538 78.334,106.528 v1(74.93,106.528) 65.126,106.528 60.96,102.362 ; C705.2@149.352,162.306 148.209,161.163 148.209,156.286 149.911,154.584 149.911,135.687 151.384,134.214 151.384,130.226 151.816,129.794 151.816,121.996 +5SEL.2@157.988,115.824 157.988,105.918 C007.2@159.766,104.14 ; PWOUT.2@163.576,79.248 R002.2@163.576,83.058
+5V_USB: +5SEL.3 R106.2 USB.1 | length 129.3
  Top Layer w0.254: +5SEL.3@155.448,115.824 155.448,120.294 156.769,121.615 v1(161.569,121.615)
  Bottom Layer w0.254: R106.2@106.68,159.766 102.997,163.449 102.997,169.799 USB.1@101.092,171.704 103.81,174.422 124.943,174.422 128.524,170.84 142.75,170.84 145.44,168.15 149.934,168.15 154.356,163.728 154.356,155.55 161.569,148.336 v1(161.569,121.615)
+8V: C002.1 C302.2 C401.2 C502.2 PWOUT.1 R001.2 U3.13 U4.8 U5.13 U8.3 U10.1 | length 254
  Top Layer w0.254: C401.2@55.855,138.354 58.369,140.868 67.208,140.868 U3.13@71.882,145.542 73.025,144.399 84.506,144.399 85.192,145.085 103.708,145.085 105.308,146.685 125.806,146.685 127.762,144.729 138.989,144.729 139.065,144.805 155.854,144.805 156.372,144.288 C002.1@158.496,144.288 159.528,143.256 U8.3@166.624,143.256 ; C502.2@64.135,112.395 65.659,112.395 U5.13@71.882,118.618
  Bottom Layer w0.254: U4.8@60.198,129.794 62.738,127.254 62.738,113.792 C502.2@64.135,112.395 ; C302.2@64.643,153.543 70.206,147.98 70.206,147.218 U3.13@71.882,145.542 72.949,144.475 72.949,119.685 U5.13@71.882,118.618 ; PWOUT.1@166.116,79.248 166.116,81.026 R001.2@168.148,83.058 165.405,85.801 165.405,95.199 165.608,95.402 167.234,95.402 167.742,95.91 167.742,120.464 U10.1@166.624,121.581 167.589,122.547 167.589,142.291 U8.3@166.624,143.256
-8V: C006.2 C303.1 C402.1 C503.1 PWOUT.4 R004.2 U3.3 U4.4 U5.3 U9.2 | length 259
  Top Layer w0.254: C402.1@55.855,129.21 57.887,129.21 59.538,130.861 62.205,130.861 v1(63.551,132.207) ; C503.1@64.135,107.315 72.339,107.315 73.203,108.179 73.203,114.605 74.676,116.078 U5.3@79.502,116.078 ; U4.4@67.818,137.414 68.377,136.855 73.355,136.855 U3.3@79.502,143.002 ; C303.1@85.344,153.67 110.896,153.67 114.046,150.52 127.813,150.52 128.397,149.936 131.242,149.936 132.182,150.876 134.874,150.876 140.462,145.288 161.849,145.288 162.535,144.602 167.03,144.602 167.742,143.891 167.742,131.246 U9.2@166.424,129.929 161.647,129.929 C006.2@159.496,132.079
  Bottom Layer w0.254: v1(63.551,132.207) 67.818,136.474 U4.4@67.818,137.414 ; U5.3@79.502,116.078 78.435,117.145 78.435,141.935 U3.3@79.502,143.002 81.483,144.983 81.483,149.809 C303.1@85.344,153.67 ; PWOUT.4@158.496,79.248 158.496,82.55 R004.2@159.004,83.058 160.02,84.074 160.02,91.999 159.817,92.202 159.817,101.067 160.909,102.159 160.909,109.652 159.207,111.354 159.207,117.5 158.547,118.161 158.547,131.13 C006.2@159.496,132.079
AD6: ADC_AUX.1 U1.5 | length 47.7
  Top Layer w0.254: v1(93.726,127.965) 93.751,127.94 101.092,127.94 101.981,128.829 101.981,132.232 102.464,132.715 108.038,132.715 108.229,132.524 U1.5@111.78,132.524
  Bottom Layer w0.254: v1(93.726,127.965) 93.345,127.584 93.345,103.124 ADC_AUX.1@93.98,103.124
AD7: ADC_AUX.2 U1.6 | length 40.3
  Top Layer w0.254: v1(103.403,131.75) 103.81,132.156 107.772,132.156 107.904,132.024 U1.6@111.78,132.024
  Bottom Layer w0.254: ADC_AUX.2@96.52,103.124 96.52,104.165 96.266,104.419 96.266,111.658 102.108,117.5 102.108,130.454 v1(103.403,131.75)
ADC_CE: U1.27 U2.22 | length 57.3
  Top Layer w0.254: U2.22@73.66,102.743 73.66,114.427 73.838,114.605 84.582,114.605 87.96,117.983 108.28,117.983 v1(109.22,118.923) ; v1(113.868,122.657) 113.88,122.645 U1.27@113.88,120.924
  Bottom Layer w0.254: v1(109.22,118.923) 110.261,119.964 110.261,120.371 112.547,122.657 v1(113.868,122.657)
ADC_CLK: U1.65 U2.16 | length 100.5
  Top Layer w0.254: v1(80.924,100.838) 81.28,101.194 U2.16@81.28,102.743 ; v1(86.208,103.861) 87.617,105.27 95.758,105.27 96.939,106.451 105.131,106.451 106.223,105.359 106.223,101.321 105.867,100.965 105.867,97.343 106.477,96.733 110.134,96.733 110.744,97.343 110.744,98.349 112.141,99.746 119.532,99.746 v1(120.853,101.067) ; U1.65@126.98,129.524 128.279,129.524 v1(128.676,129.921)
  Bottom Layer w0.254: v1(80.924,100.838) 83.947,103.861 v1(86.208,103.861) ; v1(120.853,101.067) 120.853,114.148 120.513,114.488 120.513,118.684 127,125.171 127,130.861 127.33,131.191 127.33,133.325 128.422,134.417 129.235,134.417 129.794,133.858 129.794,131.039 v1(128.676,129.921)
ADC_D0: U1.40 U2.2 | length 101.8
  Top Layer w0.254: U2.2@72.39,93.543 72.39,86.03 72.938,85.482 83.098,85.482 v1(83.566,85.014) ; U1.40@120.38,120.924 v1(120.38,122.53)
  Bottom Layer w0.254: v1(83.566,85.014) 83.566,82.728 88.316,77.978 109.83,77.978 110.693,78.842 110.693,82.855 111.219,83.381 111.219,85.369 110.693,85.895 110.693,91.973 113.919,95.199 115.468,95.199 117.856,97.587 117.856,98.806 119.558,100.508 119.558,104.623 120.396,105.461 120.396,113.614 120.079,113.931 120.079,122.229 v1(120.38,122.53)
ADC_D1: U1.41 U2.1 | length 120.2
  Top Layer w0.254: v1(70.79,90.907) 71.12,91.237 U2.1@71.12,93.543 ; v1(110.261,83.82) 111.455,83.82 115.418,87.782 v1(131.318,87.782) ; U1.41@120.88,120.924 120.88,115.924 121.213,115.591 123.144,115.591 124.206,114.529 v1(125.324,114.529)
  Bottom Layer w0.254: v1(70.79,90.907) 73.685,88.011 74.778,88.011 79.426,92.659 80.137,92.659 87.909,84.887 87.909,80.467 89.687,78.689 109.195,78.689 109.779,79.273 109.779,83.337 v1(110.261,83.82) ; v1(125.324,114.529) 130.378,109.474 130.378,96.495 130.962,95.91 130.962,88.138 v1(131.318,87.782)
ADC_D2: U1.42 U2.24 | length 133.8
  Top Layer w0.254: U2.24@71.12,102.743 71.12,103.937 70.917,104.14 59.334,104.14 58.928,103.734 58.928,96.977 72.314,83.591 88.621,83.591 92.812,87.782 100.66,87.782 101.346,88.468 103.038,88.468 103.683,89.113 104.937,89.113 105.639,89.814 105.639,93.904 106.07,94.336 114.402,94.336 114.785,94.719 125.118,94.719 126.035,93.802 127.762,93.802 v1(128.194,94.234) ; U1.42@121.38,120.924 121.38,116.235 121.59,116.025 v1(124.206,116.025)
  Bottom Layer w0.254: v1(124.206,116.025) 124.206,106.959 127.787,103.378 127.787,94.64 v1(128.194,94.234)
ADC_D3: U1.43 U2.23 | length 126.4
  Top Layer w0.254: U2.23@72.39,102.743 72.39,99.162 73.406,98.146 78.029,98.146 79.35,96.825 79.35,92.126 75.54,92.126 75.54,94.971 71.78,94.971 71.78,85.598 73.33,84.049 86.208,84.049 90.396,88.237 99.921,88.237 100.609,88.925 102.438,88.925 102.921,89.408 102.921,92.507 105.207,94.793 113.61,94.793 113.988,95.171 126.444,95.171 v1(126.822,94.793) ; U1.43@121.88,120.924 121.88,117.464 v1(122.377,116.967)
  Bottom Layer w0.254: v1(122.377,116.967) 122.377,115.773 123.753,114.397 123.753,105.588 125.73,103.611 125.73,95.885 v1(126.822,94.793)
ADC_D4: U1.54 U2.15 | length 65.4
  Top Layer w0.254: U2.15@82.55,102.743 82.55,105.004 83.718,106.172 88.671,106.172 95.707,113.208 95.707,116.18 95.91,116.383 100.076,116.383 103.505,112.954 v1(109.144,112.954) ; v1(116.281,123.825) 118.389,125.933 121.289,125.933 123.198,124.024 U1.54@126.98,124.024
  Bottom Layer w0.254: v1(109.144,112.954) 109.499,113.309 113.792,113.309 115.291,114.808 115.291,122.834 v1(116.281,123.825)
ADC_D5: U1.34 U2.14 | length 103
  Top Layer w0.254: v1(83.82,100.127) U2.14@83.82,102.743 ; v1(88.925,80.966) 91.914,77.978 115.57,77.978 v1(116.713,79.121) ; U1.34@117.38,120.924 117.38,118.643 117.32,118.584 117.32,112.166 118.616,110.871 120.523,110.871 121.082,110.312 v1(122.377,110.312)
  Bottom Layer w0.254: v1(83.82,100.127) 83.82,92.202 88.925,87.097 v1(88.925,80.966) ; v1(116.713,79.121) 116.713,91.872 119.888,95.047 119.888,99.162 120.294,99.568 121.92,99.568 122.936,100.584 122.936,104.115 122.377,104.673 v1(122.377,110.312)
ADC_D6: U1.31 U2.13 | length 55.7
  Top Layer w0.254: U2.13@85.09,102.743 85.09,104.851 85.954,105.715 94.285,105.715 95.733,107.163 105.639,107.163 107.163,105.639 v1(108.153,105.639) ; v1(113.589,111.379) 113.589,115.138 115.88,117.429 U1.31@115.88,120.924
  Bottom Layer w0.254: v1(108.153,105.639) 109.169,104.623 109.169,102.997 111.049,101.117 113.055,101.117 113.833,101.895 113.833,111.135 v1(113.589,111.379)
ADC_D7: U1.38 U2.12 | length 94.6
  Top Layer w0.254: U2.12@85.09,93.543 85.09,92.786 89.027,92.786 89.967,91.846 89.967,89.764 90.617,89.113 92.507,89.113 93.167,89.773 93.167,94.691 94.285,95.809 113.106,95.809 113.843,96.545 132.486,96.545 133.02,97.079 133.02,102.413 132.182,103.251 v1(132.156,103.251) ; U1.38@119.38,120.924 119.38,119.405 119.659,119.126 119.659,114.66 120.908,113.411 125.679,113.411 127.254,114.986 v1(127.254,115.773)
  Bottom Layer w0.254: v1(127.254,115.773) 127.254,114.253 131.343,110.164 131.343,104.064 v1(132.156,103.251)
ADC_O/UF: U1.28 U2.11 | length 49.2
  Top Layer w0.254: U2.11@83.82,93.543 83.82,97.993 90.653,104.826 v1(97.231,104.826) ; v1(102.667,116.383) 103.708,117.424 v1(109.195,117.424) ; v1(114.325,119.05) 114.38,119.104 U1.28@114.38,120.924
  Bottom Layer w0.254: v1(97.231,104.826) 97.231,110.947 v1(102.667,116.383) ; v1(109.195,117.424) 110.82,119.05 v1(114.325,119.05)
ADC_VIN: D201.1 D202.2 R201.2 U2.8 | length 39.7
  Top Layer w0.254: R201.2@55.626,84.836 57.607,82.855 65.38,82.855 66.065,82.169 D201.1@67.414,82.169 70.335,79.248 D202.2@77.874,79.248 ; v1(79.197,90.983) 80.01,91.796 U2.8@80.01,93.543
  Bottom Layer w0.254: D202.2@77.874,79.248 79.197,80.571 v1(79.197,90.983)
ADC_VRB: C202.2 R401.1 R405.2 U2.4 U4.7 | length 90.8
  Top Layer w0.254: R405.2@53.848,113.03 52.959,113.919 52.959,129.235 54.077,130.353 58.217,130.353 U4.7@60.198,132.334 ; C202.2@74.168,89.154 74.93,89.916 U2.4@74.93,93.543
  Bottom Layer w0.254: R405.2@53.848,113.03 52.832,112.014 52.832,96.901 54.305,95.428 58.191,95.428 63.576,100.813 68.072,100.813 74.168,94.717 C202.2@74.168,89.154 ; U4.7@60.198,132.334 61.468,133.604 R401.1@61.468,144.018
ADC_VRB_MCU: R405.1 R406.2 U1.4 | length 81.5
  Top Layer w0.254: R405.1@53.848,105.41 R406.2@56.388,105.41 ; v1(57.125,126.086) 58.826,127.787 68.555,127.787 71.755,130.988 100.051,130.988 102.231,133.168 108.661,133.168 108.805,133.024 U1.4@111.78,133.024
  Bottom Layer w0.254: R406.2@56.388,105.41 57.531,106.553 57.531,125.679 v1(57.125,126.086)
ADC_VRT: C201.2 R402.1 R403.2 U2.9 U4.1 | length 98.1
  Top Layer w0.254: U4.1@67.818,129.794 66.548,128.524 56.845,128.524 55.499,127.178 55.499,116.586 R403.2@56.515,115.57 55.372,114.427 55.372,108.712 57.937,106.147 71.755,106.147 73.05,104.851 73.05,99.72 73.355,99.416 80.467,99.416 81.28,98.603 U2.9@81.28,93.543 C201.2@81.28,89.154
  Bottom Layer w0.254: R402.1@61.468,146.897 62.789,145.576 62.789,143.053 64.16,141.681 67.818,141.681 68.885,140.614 68.885,130.861 U4.1@67.818,129.794
ADC_VRT_MCU: R403.1 R404.2 U1.3 | length 78
  Top Layer w0.254: R403.1@56.515,123.19 56.515,123.927 58.572,125.984 70.129,125.984 71.349,124.765 90.729,124.765 91.965,123.529 100.506,123.529 101.995,125.019 v1(104.47,125.019) ; U1.3@111.78,133.524 112.907,133.524 114.351,132.08 v1(114.351,131.978)
  Bottom Layer w0.254: R404.2@53.975,115.57 53.975,120.65 R403.1@56.515,123.19 ; v1(104.47,125.019) 105.08,125.628 105.08,129.235 106.02,130.175 107.622,130.175 109.095,131.648 114.021,131.648 v1(114.351,131.978)
AGND: "SIG IN.2" C201.1 C202.1 C205.1 D202.1 U2.5 U2.6 | length 60.8
  Top Layer w0.254: 57.912,81.28 58.979,82.347 64.315,82.347 D202.1@67.414,79.248 ; C205.1@65.024,96.774 75.336,96.774 76.2,95.91 U2.5@76.2,93.543 U2.6@77.47,93.543 ; C202.1@74.168,86.614 C201.1@81.28,86.614
  Bottom Layer w0.254: C205.1@65.024,96.774 68.732,93.066 68.732,81.178 ; D202.1@67.414,79.248 68.732,80.566 68.732,81.178 ; C202.1@74.168,86.614 68.732,81.178
  other v1: 83,79.807
B1: R115.1 U1.18 | length 82.8
  Top Layer w0.254: v1(111.633,120.167) 111.434,119.969 111.434,111.637 110.287,110.49 110.287,108.61 111.862,107.036 125.476,107.036 v1(125.882,106.629) ; U1.18@111.78,126.024 115.606,126.024 v1(116.053,125.578)
  Bottom Layer w0.254: v1(111.633,120.167) 113.894,120.167 114.833,121.107 114.833,124.358 v1(116.053,125.578) ; R115.1@124.121,90.17 124.121,81.619 124.765,80.975 128.016,80.975 130.124,83.083 130.124,88.9 130.378,89.154 130.378,94.971 128.346,97.003 128.346,103.886 125.882,106.35 v1(125.882,106.629)
B2: R117.1 U1.19 | length 57.1
  Top Layer w0.254: v1(108.407,93.345) 108.229,93.523 106.551,93.523 106.094,93.066 106.094,91.846 106.348,91.592 112.42,91.592 112.497,91.669 119.998,91.669 R117.1@121.497,90.17 ; v1(109.499,125.705) 109.68,125.524 U1.19@111.78,125.524
  Bottom Layer w0.254: v1(108.407,93.345) 108.407,99.568 106.629,101.346 106.629,105.696 107.334,106.401 107.334,115.568 107.798,116.032 107.798,121.92 109.144,123.266 109.322,123.266 109.931,123.876 109.931,125.273 v1(109.499,125.705)
B3: R119.1 U1.20 | length 68.6
  Top Layer w0.254: v1(107.036,92.558) 107.467,92.126 129.736,92.126 130.835,93.225 132.893,93.225 134.62,91.498 R119.1@134.62,90.17 ; v1(108.179,123.952) 109.347,123.952 110.353,124.958 110.505,124.958 110.571,125.024 U1.20@111.78,125.024
  Bottom Layer w0.254: v1(107.036,92.558) 107.036,96.037 105.588,97.485 105.588,100.787 104.089,102.286 104.089,104.445 106.9,107.255 106.9,116.078 107.361,116.54 107.361,123.135 v1(108.179,123.952)
CS_MMC: MMC.4 U1.21 | length 60.1
  Top Layer w0.254: v1(109.144,121.895) 109.144,123.088 110.579,124.524 U1.21@111.78,124.524 ; v1(110.795,106.68) 111.176,106.299 124.102,106.299 124.714,105.687 126.439,105.687 127.305,106.553 129.337,106.553 129.819,106.07 146.202,106.07 MMC.4@147.828,107.696
  Bottom Layer w0.254: v1(109.144,121.895) 108.253,121.003 108.253,115.547 107.768,115.062 107.768,109.707 v1(110.795,106.68)
DAC_VRB_D0: U1.69 U5.5 | length 83.7
  Top Layer w0.254: v1(83.134,142.392) 85.382,144.64 113.538,144.64 113.768,144.41 118.161,144.41 118.807,143.764 121.92,143.764 122.86,142.824 122.86,141.986 122.504,141.63 122.326,141.63 v1(121.437,140.741) ; v1(124.333,130.073) 125.784,131.524 U1.69@126.98,131.524
  Bottom Layer w0.254: U5.5@79.502,121.158 83.134,124.79 v1(83.134,142.392) ; v1(121.437,140.741) 121.869,140.31 122.25,140.31 126.009,136.55 126.009,131.75 v1(124.333,130.073)
DAC_VRB_D1: U1.70 U5.6 | length 129.5
  Top Layer w0.254: v1(84.201,145.796) 85.75,147.345 v1(103.022,147.345) ; v1(113.132,149.098) 113.259,149.225 125.349,149.225 128.194,146.38 136.754,146.38 v1(137.439,145.694) ; U1.70@126.98,132.024 140.162,132.024 141.681,130.505 143.815,130.505 143.815,138.811 142.011,140.614 v1(137.439,140.614)
  Bottom Layer w0.254: U5.6@79.502,123.698 80.569,124.765 80.569,142.164 v1(84.201,145.796) ; v1(103.022,147.345) 103.022,142.24 103.835,141.427 106.197,141.427 108.509,143.739 108.509,148.742 109.525,149.758 112.471,149.758 v1(113.132,149.098) ; v1(137.439,140.614) v1(137.439,145.694)
DAC_VRB_D2: U1.71 U5.7 | length 56.1
  Top Layer w0.254: U5.7@79.502,126.238 91.338,126.238 93.613,123.963 95.098,123.963 95.758,124.623 95.758,125.705 96.317,126.263 104.673,126.263 v1(106.502,128.092) ; v1(115.672,130.023) 116.582,128.706 119.228,128.706 120.527,127.406 122.352,127.406 123.368,128.422 123.368,130.454 125.437,132.524 U1.71@126.98,132.524
  Bottom Layer w0.254: v1(106.502,128.092) 107.62,128.092 109.525,129.997 v1(115.672,130.023)
DAC_VRB_D3: U1.72 U5.8 | length 58.7
  Top Layer w0.254: v1(79.502,136.347) 79.756,136.601 109.118,136.601 v1(110.973,138.455) ; v1(124.587,133.045) 124.608,133.024 U1.72@126.98,133.024
  Bottom Layer w0.254: U5.8@79.502,128.778 v1(79.502,136.347) ; v1(110.973,138.455) 111.938,137.49 114.859,137.49 116.078,136.271 122.25,136.271 124.587,133.934 v1(124.587,133.045)
DAC_VRB_D4: U1.9 U5.9 | length 43.3
  Top Layer w0.254: U5.9@71.882,128.778 73.279,130.175 90.018,130.175 93.193,127 94.793,127 95.299,127.506 103.249,127.506 105.482,129.739 107.424,129.739 108.21,130.524 U1.9@111.78,130.524
DAC_VRB_D5: U1.10 U5.10 | length 42.1
  Top Layer w0.254: U5.10@71.882,126.238 72.949,127.305 91.872,127.305 92.634,126.543 94.996,126.543 95.504,127.051 103.657,127.051 105.893,129.286 107.609,129.286 108.347,130.024 U1.10@111.78,130.024
DAC_VRB_D6: U1.11 U5.11 | length 43.7
  Top Layer w0.254: U5.11@71.882,123.698 73.05,122.53 83.287,122.53 83.852,123.095 102.385,123.095 103.367,124.077 104.9,124.077 105.588,124.765 105.588,125.476 109.636,129.524 U1.11@111.78,129.524
DAC_VRB_D7: U1.12 U5.12 | length 44.8
  Top Layer w0.254: U5.12@71.882,121.158 72.949,120.091 84.633,120.091 87.198,122.657 102.736,122.657 103.702,123.622 105.867,123.622 106.147,123.901 106.147,125.247 109.923,129.024 U1.12@111.78,129.024
DAC_VRT_D0: U1.44 U3.5 | length 120.8
  Top Layer w0.254: U3.5@79.502,148.082 78.003,149.581 78.003,153.619 78.816,154.432 80.594,154.432 81.432,155.27 115.367,155.27 115.748,154.889 117.272,154.889 119.278,152.883 128.092,152.883 129.007,153.797 134.722,153.797 135.712,152.806 v1(135.712,151.384) ; U1.44@122.38,120.924 122.38,119.682 v1(124.206,117.856)
  Bottom Layer w0.254: v1(124.206,117.856) 124.206,119.126 130.124,125.044 133.909,125.044 134.62,124.333 139.09,124.333 139.522,124.765 139.522,131.115 134.468,136.169 134.137,136.169 134.137,140.792 134.823,141.478 134.823,148.793 135.712,149.682 v1(135.712,151.384)
DAC_VRT_D1: U1.45 U3.6 | length 73.7
  Top Layer w0.254: U3.6@79.502,150.622 81.382,148.742 v1(110.541,148.742) ; v1(122.149,122.733) 122.88,122.001 U1.45@122.88,120.924
  Bottom Layer w0.254: v1(110.541,148.742) 110.541,140.157 110.947,139.751 111.354,139.751 113.03,138.074 115.494,138.074 116.815,136.754 123.901,136.754 125.552,135.103 125.552,132.486 124.104,131.039 123.546,131.039 122.987,130.48 122.987,123.571 v1(122.149,122.733)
